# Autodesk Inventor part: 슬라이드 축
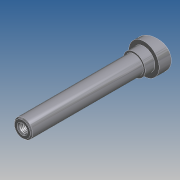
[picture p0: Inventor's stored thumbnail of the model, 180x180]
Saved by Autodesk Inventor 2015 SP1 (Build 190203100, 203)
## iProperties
Created: 2012-05
Part Number: 슬라이드 축
Document SubType Name: 모델링
Designer: SeoGD™
Mass: 169.348 g
Surface Area: 67.586 cm^2
Volume: 21.5729 cm^3
Density: 7.85 g/cm^3
Material: 강철, 연강
Appearance: 반연마
변환 표준: STEP AP214IS
파일 이름: C:\Users\SeoGD\Desktop\?쒗뿕\異?stp
전처리기: Build: 253, Release: 2010 SP1 - Date: Wed 07/29/2009
전송 단위: 밀리미터
불확실성: 0.01
Author: SeoGD™
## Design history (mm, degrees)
sketch "스케치1"
  geometry: L1 (0, 100)-(7.5, 100); L2 (7.5, 100)-(7.5, 0); L3 (7.5, 0)-(12.5, 0); L4 (12.5, 0)-(12.5, -17); L5 (12.5, -17)-(0, -17); L6 (0, -17)-(0, 100); 1 further point
  constraints: 12 end point, 2 parallel, 2 point on line, 1 perpendicular, 1 vertical
  dimensions: "d0" = 100 distance from line of L1 point (0, 0); "d1" = 15 diameter of L2 L6; "d2" = 25 diameter of L4 L6; "d3" = 17 distance of L3.end L4.end
revolve "회전1" sketch "스케치1" stored, may be unused: angle "d4" = 90 deg
sketch "스케치2"
  geometry: L1 (12.5, 0)-(12.5, -17) reference; L2 (-12.5, -17)-(12.5, -17) reference; L3 (-12.5, 0)-(-12.5, -17) reference; L4 (12.5, -5)-(-12.5, -11.699); L5 (-12.5, 0)-(12.5, 0) reference; 1 further point
  constraints: 2 end point, 2 point on line
  dimensions: "d5" = 75 deg angle of L1 L4; "d6" = 5 distance from line of L4.start L5
extrude "돌출1" cut sketch "스케치2" stored distance "d7" = 10; taper "d8" = 0 deg
chamfer "모따기1" distance "d9" = 1; stored, may be unused: second distance "d10" = 2, angle "d11" = 45 deg
fillet "모깎기1" dims "d12" = 0.5
hole "구멍1" diameter "d15" = 6.647; stored, may be unused: countersink angle "d19" = 90 deg, drill point angle "d21" = 118 deg; dims "d13" = 10, "d14" = 10, "d16" = 17, "d17" = 4, "d18" = 2, "d20" = 20
chamfer "모따기2" distance "d22" = 1; stored, may be unused: second distance "d23" = 2, angle "d24" = 45 deg
sketch "스케치3"
  geometry: C1 r 9 at (0, 0); 1 further point
  constraints: 1 centre point, 1 coincident
  dimensions: "d25" = 18 diameter of C1
extrude "돌출2" join sketch "스케치3" distance "d26" = 8; taper "d27" = 0 deg
node "솔리드1"
node "솔리드 본체"
node "곡면 본체"
node "솔리드2"
